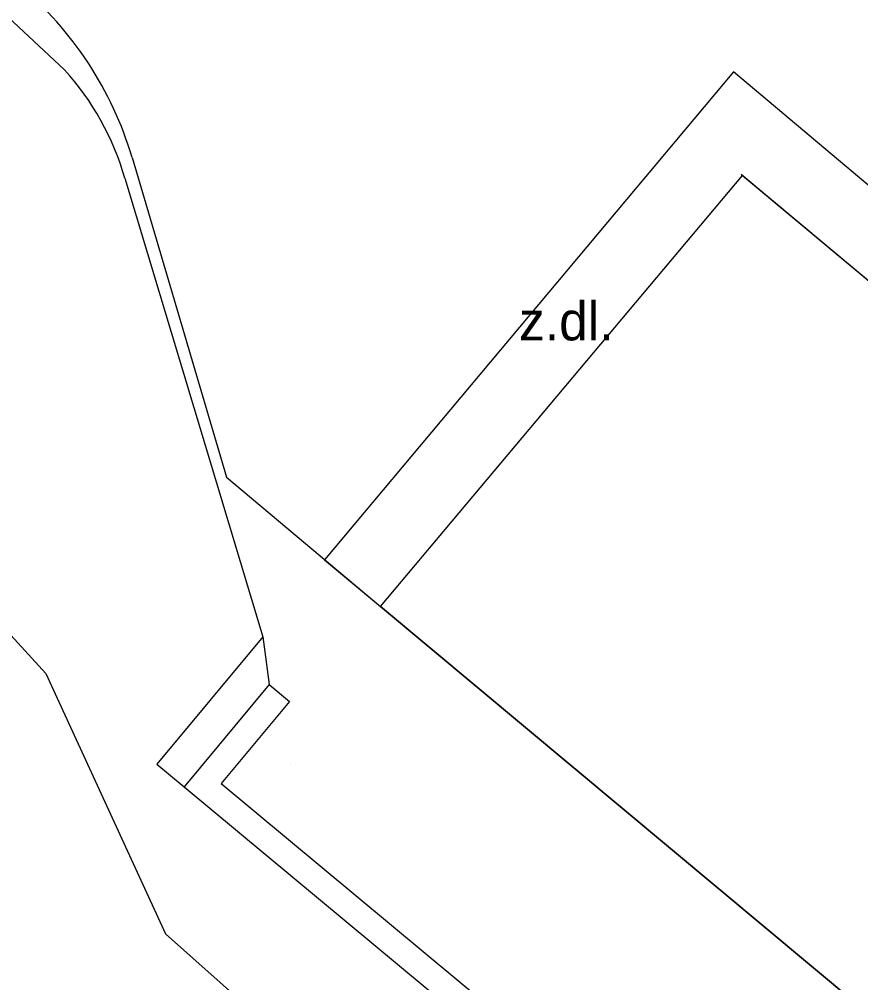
# Model space of a CAD drawing. Extents: x -438200 to -437954, y -1133133 to -1132850.
# Drawn here: x -438143.01 to -438128.82, y -1132982.38 to -1132966.14 of the extents above; entities that cross this region are included whole.
import ezdxf

# ---------------------------------------------------------------- set-up
doc = ezdxf.new("R2010")
doc.units = 0
for name, color, linetype in [('Vrstva 1', 7, 'Continuous'), ('Vrstva 10', 7, 'Continuous'), ('Vrstva 11', 7, 'Continuous'), ('Vrstva 14', 7, 'Continuous'), ('Vrstva 40', 7, 'Continuous'), ('Vrstva 5', 7, 'Continuous')]:
    doc.layers.add(name, color=color, linetype=linetype)

msp = doc.modelspace()

# ---------------------------------------------------------------- linework, layer by layer
at = {"layer": 'Vrstva 1'}
for p, q in [((-438142.244, -1132966.996), (-438142.244, -1132966.996)), ((-438130.965, -1132967.03), (-438130.965, -1132967.03)), ((-438141.105, -1132968.475), (-438139.515, -1132973.862)), ((-438141.105, -1132968.475), (-438139.515, -1132973.862)), ((-438130.815, -1132968.777), (-438130.815, -1132968.777)), ((-438141.227, -1132968.824), (-438141.227, -1132968.824)), ((-438139.515, -1132973.862), (-438136.916, -1132976.04)), ((-438139.515, -1132973.862), (-438136.916, -1132976.04)), ((-438137.86, -1132975.253), (-438137.86, -1132975.253)), ((-438136.916, -1132976.04), (-438136.916, -1132976.04)), ((-438138.902, -1132976.553), (-438138.902, -1132976.553)), ((-438142.557, -1132977.168), (-438142.557, -1132977.168)), ((-438138.453, -1132977.639), (-438138.453, -1132977.639)), ((-438138.43, -1132978.7), (-438138.43, -1132978.7)), ((-438140.218, -1132979.05), (-438140.218, -1132979.05)), ((-438137.672, -1132980.631), (-438137.672, -1132980.631)), ((-438140.54, -1132981.557), (-438140.54, -1132981.557))]:
    msp.add_line(p, q, dxfattribs=at)
msp.add_arc((-438146.86, -1132970.174), 6, 16.4456, 50.0448, dxfattribs=at)
msp.add_arc((-438146.86, -1132970.174), 6, 16.4456, 50.0448, dxfattribs=at)
at = {"layer": 'Vrstva 10'}
msp.add_lwpolyline([(-438136.916, -1132976.04), (-438130.815, -1132968.777), (-438110.909, -1132985.383), (-438109.206, -1132983.342), (-438101.698, -1132989.616), (-438102.771, -1132990.9), (-438091.189, -1133000.578), (-438097.908, -1133008.583)], close=True, dxfattribs=at)
msp.add_lwpolyline([(-438136.916, -1132976.04), (-438130.815, -1132968.777), (-438110.909, -1132985.383), (-438109.206, -1132983.342), (-438101.698, -1132989.616), (-438102.771, -1132990.9), (-438091.189, -1133000.578), (-438097.908, -1133008.583)], close=True, dxfattribs=at)
at = {"layer": 'Vrstva 11'}
for points in [[(-438149.747, -1132960.758), (-438149.622, -1132960.625), (-438144.574, -1132964.816), (-438142.244, -1132966.996)], [(-438121.978, -1132974.593), (-438130.965, -1132967.03), (-438137.86, -1132975.253), (-438136.916, -1132976.04)], [(-438141.227, -1132968.824), (-438138.902, -1132976.553), (-438138.792, -1132977.357)], [(-438138.902, -1132976.553), (-438140.686, -1132978.698), (-438140.226, -1132979.081)], [(-438138.792, -1132977.357), (-438140.226, -1132979.081), (-438130.239, -1132987.383), (-438111.696, -1133002.719), (-438101.614, -1133013.302)], [(-438138.792, -1132977.357), (-438138.453, -1132977.639)], [(-438138.453, -1132977.639), (-438139.605, -1132979.024), (-438129.958, -1132987.044), (-438111.395, -1133002.396), (-438101.295, -1133012.998)]]:
    msp.add_lwpolyline(points, dxfattribs=at)
msp.add_arc((-438145.614, -1132970.068), 4.559, 15.8277, 42.3507, dxfattribs=at)
at = {"layer": 'Vrstva 14'}
for points in [[(-438149.747, -1132960.758), (-438150.927, -1132965.348), (-438150.005, -1132969.025), (-438142.557, -1132977.168), (-438140.54, -1132981.557)], [(-438140.54, -1132981.557), (-438107.695, -1133010.79), (-438101.937, -1133015.758)]]:
    msp.add_lwpolyline(points, dxfattribs=at)
at = {"layer": 'Vrstva 5'}
for p, q in [((-438136.916, -1132976.04), (-438130.815, -1132968.777)), ((-438130.84, -1132968.756), (-438110.909, -1132985.383)), ((-438136.916, -1132976.04), (-438116.764, -1132992.852))]:
    msp.add_line(p, q, dxfattribs=at)

# ---------------------------------------------------------------- texts
at = {"layer": 'Vrstva 40'}
msp.add_text('z.dl.', height=0.65, dxfattribs=at).set_placement((-438134.582, -1132971.556))

doc.saveas('drawing.dxf')
